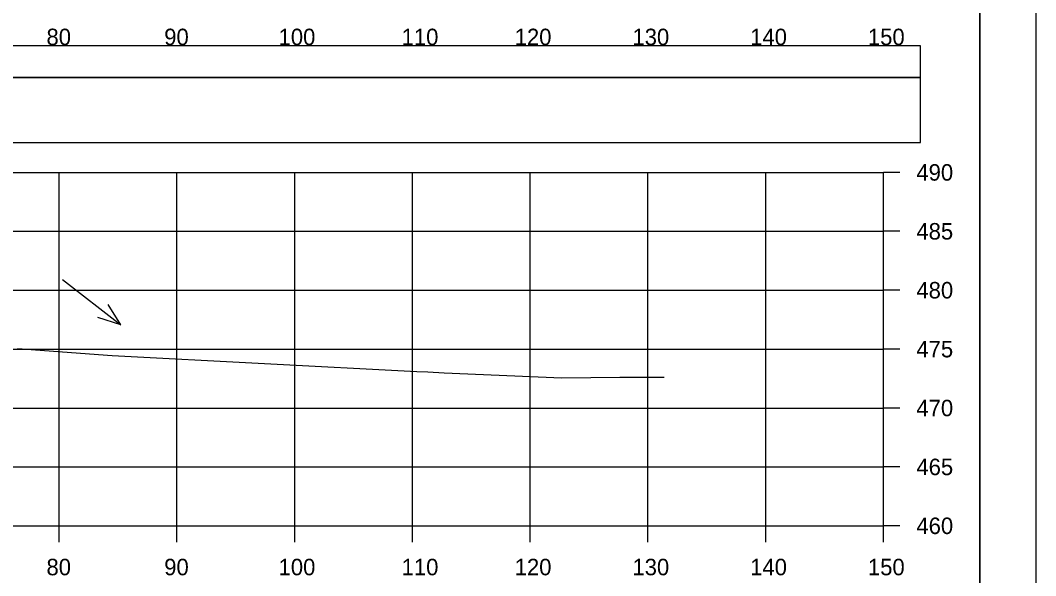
# Model space of a CAD drawing. Extents: x 1371057 to 1372761, y 380005 to 390517.
# Drawn here: x 1371970.9 to 1372057.1, y 381608.2 to 381655.3 of the extents above; entities that cross this region are included whole.
import ezdxf

# ---------------------------------------------------------------- set-up
doc = ezdxf.new("R2010")
doc.units = 0
for name, color, linetype in [('R_Axis', 7, 'Continuous'), ('R_Axis Annot', 7, 'Continuous'), ('R_Border', 7, 'Continuous'), ('R_Detour', 7, 'Continuous'), ('R_Dimension', 7, 'Continuous'), ('R_Exist Surface', 7, 'Continuous'), ('R_Grid', 7, 'Continuous'), ('R_No Plot', 7, 'Continuous'), ('R_Water Annot', 7, 'Continuous')]:
    doc.layers.add(name, color=color, linetype=linetype)

msp = doc.modelspace()

# ---------------------------------------------------------------- linework, layer by layer
at = {"layer": 'R_Axis'}
for p, q in [((1372044.212, 381612.425), (1372044.212, 381642.425)), ((1372045.612, 381642.425), (1372044.212, 381642.425)), ((1372045.612, 381637.425), (1372044.212, 381637.425)), ((1372045.612, 381632.425), (1372044.212, 381632.425)), ((1372045.612, 381627.425), (1372044.212, 381627.425)), ((1372045.612, 381622.425), (1372044.212, 381622.425)), ((1372045.612, 381617.425), (1372044.212, 381617.425)), ((1371744.212, 381612.425), (1372044.212, 381612.425)), ((1371974.212, 381611.025), (1371974.212, 381612.425)), ((1371984.212, 381611.025), (1371984.212, 381612.425)), ((1371994.212, 381611.025), (1371994.212, 381612.425)), ((1372004.212, 381611.025), (1372004.212, 381612.425)), ((1372014.212, 381611.025), (1372014.212, 381612.425)), ((1372024.212, 381611.025), (1372024.212, 381612.425)), ((1372034.212, 381611.025), (1372034.212, 381612.425)), ((1372044.212, 381611.025), (1372044.212, 381612.425)), ((1372045.612, 381612.425), (1372044.212, 381612.425))]:
    msp.add_line(p, q, dxfattribs=at)
at = {"layer": 'R_Border'}
msp.add_line((1372052.392, 381502.425), (1372052.392, 381707.885), dxfattribs=at)
at = {"layer": 'R_Detour'}
msp.add_lwpolyline([(1371741.057, 381650.472), (1372047.367, 381650.472), (1372047.367, 381653.178), (1371741.057, 381653.178)], close=True, dxfattribs=at)
at = {"layer": 'R_Dimension'}
msp.add_lwpolyline([(1371741.057, 381644.95), (1372047.367, 381644.95), (1372047.367, 381650.472), (1371741.057, 381650.472)], close=True, dxfattribs=at)
at = {"layer": 'R_Exist Surface'}
msp.add_lwpolyline([(1371970.672, 381627.476), (1371978.713, 381626.875), (1372004.571, 381625.528), (1372005.525, 381625.485), (1372006.893, 381625.425), (1372016.905, 381624.994), (1372021.829, 381625.033), (1372025.597, 381625.044)], dxfattribs=at)
at = {"layer": 'R_Grid'}
for p, q in [((1371744.212, 381642.425), (1372044.212, 381642.425)), ((1371974.212, 381612.425), (1371974.212, 381642.425)), ((1371984.212, 381612.425), (1371984.212, 381642.425)), ((1371994.212, 381612.425), (1371994.212, 381642.425)), ((1372004.212, 381612.425), (1372004.212, 381642.425)), ((1372014.212, 381612.425), (1372014.212, 381642.425)), ((1372024.212, 381612.425), (1372024.212, 381642.425)), ((1372034.212, 381612.425), (1372034.212, 381642.425)), ((1372044.212, 381612.425), (1372044.212, 381642.425)), ((1371744.212, 381637.425), (1372044.212, 381637.425)), ((1371744.212, 381632.425), (1372044.212, 381632.425)), ((1371744.212, 381627.425), (1372044.212, 381627.425)), ((1371744.212, 381622.425), (1372044.212, 381622.425)), ((1371744.212, 381617.425), (1372044.212, 381617.425)), ((1371744.212, 381612.425), (1372044.212, 381612.425))]:
    msp.add_line(p, q, dxfattribs=at)
at = {"layer": 'R_No Plot'}
for points in [[(1371723.805, 381711.78), (1372057.145, 381711.78), (1372057.145, 381498.442), (1371723.805, 381498.442)], [(1371970.132, 381707.885), (1371989.752, 381707.885), (1371989.752, 381698.005), (1372005.864, 381698.005), (1372029.064, 381698.005), (1372029.185, 381669.848), (1372052.392, 381669.848), (1372052.392, 381502.425), (1371736.212, 381502.425), (1371736.212, 381707.885)]]:
    msp.add_lwpolyline(points, close=True, dxfattribs=at)
at = {"layer": 'R_Water Annot'}
for p, q in [((1371974.48, 381633.337), (1371979.442, 381629.481)), ((1371979.442, 381629.481), (1371978.353, 381631.214)), ((1371979.442, 381629.481), (1371977.494, 381630.109))]:
    msp.add_line(p, q, dxfattribs=at)

# ---------------------------------------------------------------- texts
at = {"layer": 'R_Axis Annot'}
for s, p in [('80', (1371973.127, 381653.225)), ('90', (1371983.127, 381653.225)), ('100', (1371992.84, 381653.225)), ('110', (1372003.292, 381653.225)), ('120', (1372012.895, 381653.225)), ('130', (1372022.895, 381653.225)), ('140', (1372032.895, 381653.225)), ('150', (1372042.895, 381653.225)), ('490', (1372047.012, 381641.725)), ('485', (1372047.012, 381636.725)), ('480', (1372047.012, 381631.725)), ('475', (1372047.012, 381626.725)), ('470', (1372047.012, 381621.725)), ('465', (1372047.012, 381616.725)), ('460', (1372047.012, 381611.725)), ('80', (1371973.127, 381608.225)), ('90', (1371983.127, 381608.225)), ('100', (1371992.84, 381608.225)), ('110', (1372003.292, 381608.225)), ('120', (1372012.895, 381608.225)), ('130', (1372022.895, 381608.225)), ('140', (1372032.895, 381608.225)), ('150', (1372042.895, 381608.225))]:
    msp.add_text(s, height=1.4, dxfattribs=at).set_placement(p)

doc.saveas('drawing.dxf')
